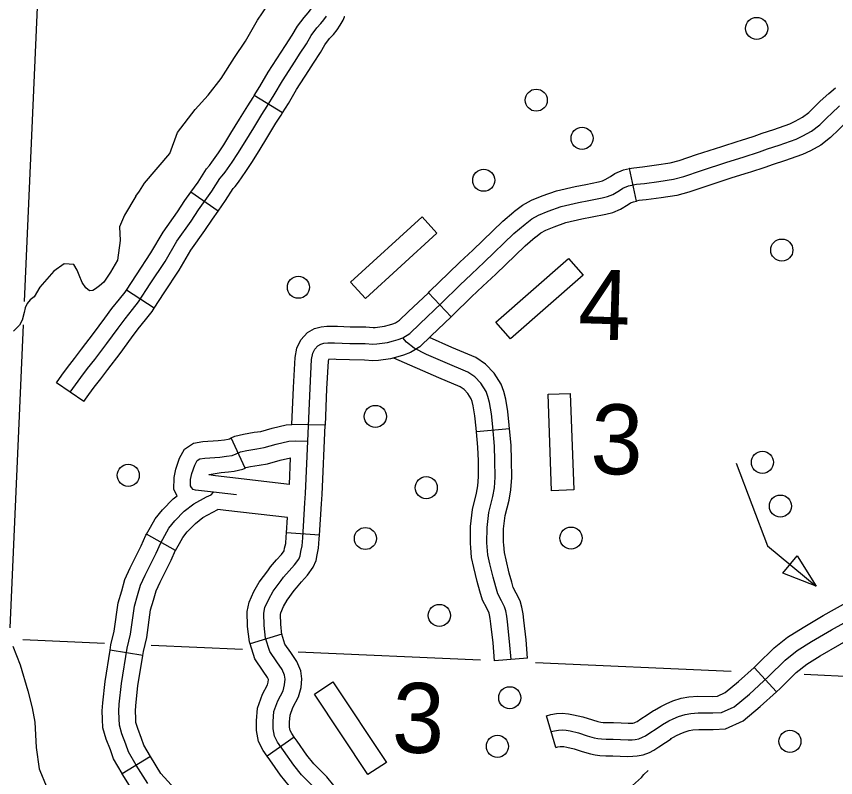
# Model space of a CAD drawing. Extents: x 653372 to 905732, y 627442 to 787275.
# Drawn here: x 705201 to 708908, y 746343 to 749788 of the extents above; entities that cross this region are included whole.
import ezdxf

# ---------------------------------------------------------------- set-up
doc = ezdxf.new("R2010")
doc.units = 0
for name, color, linetype in [('31', 7, 'Continuous'), ('32', 7, 'Continuous'), ('35', 7, 'Continuous'), ('45', 7, 'Continuous'), ('5', 7, 'Continuous'), ('56', 7, 'Continuous'), ('9', 7, 'Continuous')]:
    doc.layers.add(name, color=color, linetype=linetype)

msp = doc.modelspace()

# ---------------------------------------------------------------- linework, layer by layer
at = {"layer": '31'}
for p, q in [((707974.5, 749099), (707974.4, 749099)), ((708006.5, 748952.4), (707974.5, 749099)), ((707065, 748537.4), (707168.7, 748429))]:
    msp.add_line(p, q, dxfattribs=at)
for points in [[(708477.9, 749226), (708539.1, 749245.5), (708575.2, 749258.9), (708627.8, 749276.5), (708701.2, 749301.7), (708725.2, 749313.5), (708757.7, 749331.5), (708786.7, 749353.8), (708817.2, 749383.8), (708837.9, 749403.7), (708876.8, 749439.6), (708907.8, 749464.4)], [(706519.6, 747866), (706529.8, 748105.3), (706536.7, 748235.8), (706541.9, 748263.7), (706550.6, 748282), (706565.1, 748297.8), (706577.9, 748304.8), (706592.7, 748308.8), (706610.5, 748310.4), (706640.1, 748311), (706709.4, 748308.2), (706778.8, 748307.6), (706814.2, 748305.1), (706831.9, 748306), (706880.1, 748312.7), (706908, 748319.6), (706928.9, 748325.6), (706949.8, 748333.9), (706980.6, 748352.9), (707026.2, 748396.6), (707124.3, 748490.4), (707208, 748572.1), (707259.7, 748621.5), (707318.2, 748675.9), (707452.5, 748805.7), (707502.5, 748847.8), (707532.7, 748871.2), (707563.5, 748888), (707606.9, 748905.9), (707665.8, 748927.1), (707744.6, 748945.4), (707791.9, 748954.3), (707852.1, 748966.5), (707875.9, 748972.5), (707899.9, 748982.1), (707929.2, 749000.4), (707944.3, 749010.3), (707970.4, 749021.3), (708006.1, 749029.1), (708042.7, 749032.4), (708107.9, 749041.5), (708174, 749051.4), (708221.6, 749064), (708301.4, 749091.1), (708416.2, 749128.3), (708490, 749151.2), (708563.5, 749174.5), (708600.1, 749188.2), (708651.9, 749205.4), (708729.9, 749232.3), (708759.9, 749246.9), (708799, 749268.7), (708836, 749297.1), (708869.5, 749330.1), (708889.3, 749349), (708925.7, 749382.7)], [(709001.5, 749347.3), (708974.6, 749325.8), (708940.7, 749294.4), (708921.8, 749276.3), (708885.3, 749240.4), (708840.3, 749205.8), (708794.6, 749180.4), (708758.7, 749162.9), (708676, 749134.4), (708625.1, 749117.5), (708588, 749103.6), (708523.3, 749083.1)], [(707974.4, 749099), (707994.7, 749103.4), (708034.1, 749106.9), (708097.2, 749115.8), (708158.8, 749124.9), (708199.9, 749135.8), (708277.8, 749162.3), (708393.6, 749199.8), (708467.6, 749222.7), (708477.9, 749226)], [(707452, 748903.3), (707455.3, 748906.1), (707491.5, 748934.2), (707531.1, 748955.8), (707579.9, 748975.9), (707644.6, 748999.1), (707729.2, 749018.8), (707777.5, 749027.9), (707835.6, 749039.7), (707852.8, 749044), (707865.7, 749049.2), (707888.8, 749063.6), (707908.8, 749076.7), (707947.7, 749093.1), (707974.5, 749099)], [(708523.3, 749083.1), (708512.5, 749079.6), (708438.9, 749056.8), (708325, 749019.9), (708243.3, 748992.1), (708189.1, 748977.8), (708118.7, 748967.3), (708051.2, 748957.9), (708017.5, 748954.8), (708006.5, 748952.4)], [(707548.6, 748788.6), (707549.6, 748789.4), (707573.9, 748808.3), (707595.9, 748820.3), (707633.8, 748835.9), (707687, 748855), (707760.1, 748872), (707806.4, 748880.7), (707868.7, 748893.4), (707899.1, 748900.9), (707934, 748915), (707969.6, 748937.2), (707979.7, 748943.8), (707993.2, 748949.5), (708006.5, 748952.4)], [(707065, 748537.4), (707072.2, 748544.3), (707155.9, 748626), (707208.2, 748676.1), (707266.6, 748730.3), (707402.2, 748861.4), (707452, 748903.3)], [(707168.7, 748429), (707176.4, 748436.5), (707260.1, 748518.1), (707311.1, 748566.9), (707369.8, 748621.4), (707502.7, 748750), (707548.6, 748788.6)], [(706653.5, 748385.5), (706711.2, 748383.2), (706781.8, 748382.6), (706814.8, 748380.2), (706824.8, 748380.7), (706865.9, 748386.4), (706888.6, 748392.1), (706904.7, 748396.7), (706916.1, 748401.2), (706934.5, 748412.5), (706974.4, 748450.7), (707065, 748537.4)], [(707168.7, 748429), (707078.1, 748342.4), (707026.8, 748293.2), (706983.5, 748266.5), (706953, 748254.5), (706927.4, 748247.2), (706894.3, 748238.9), (706839.1, 748231.3), (706813.5, 748229.9), (706775.8, 748232.6), (706707.5, 748233.2), (706647.4, 748235.7)], [(706597.8, 747937.9), (706447.8, 747941.4), (706454.9, 748108.9), (706462, 748244.8), (706470, 748287.2), (706487.7, 748324.4), (706518.2, 748357.6), (706549.7, 748374.9), (706579.4, 748382.8), (706606.2, 748385.4), (706640.8, 748386.1), (706653.5, 748385.5)], [(706647.4, 748235.7), (706639.3, 748236), (706614.8, 748235.5), (706612.9, 748235.3), (706611.3, 748226.9), (706604.7, 748101.7), (706597.8, 747937.9)]]:
    msp.add_lwpolyline(points, dxfattribs=at)
at = {"layer": '32'}
for p, q in [((706405, 749351.2), (706277.5, 749430.3)), ((706113.3, 748906.3), (705990.7, 748992.7)), ((705825, 748467.8), (705699.1, 748549.3)), ((705506.5, 748044.5), (705382.7, 748129.2)), ((706235.6, 747743.8), (706172.5, 747879.9)), ((705920.8, 747371), (705790, 747444.4)), ((706572.2, 747440.1), (706422.5, 747450.1)), ((706401.3, 746992.4), (706258.2, 746947.5)), ((705772.9, 746896.2), (705624.8, 746919.9)), ((706458.5, 746525.8), (706335.4, 746440.1)), ((705807.6, 746438.5), (705680, 746359.6))]:
    msp.add_line(p, q, dxfattribs=at)
for points in [[(706277.5, 749430.3), (706303.1, 749471.5), (706340.4, 749536.2), (706398.9, 749625.6), (706419.2, 749657), (706449, 749703.5), (706472.3, 749743.3), (706502.9, 749783.8), (706521.3, 749804), (706531.7, 749817.2), (706540.2, 749829.3), (706543.3, 749834.7), (706549, 749850.9), (706562.1, 749872.2), (706567, 749878.7)], [(705444.6, 748086.8), (705467.8, 748120.7), (705492.7, 748154.4), (705523.1, 748194.3), (705555.3, 748235.6), (705610.1, 748307.4), (705660.9, 748377.6), (705692.7, 748420), (705726.3, 748461.5), (705753.8, 748495.9), (705806.7, 748577.5), (705873.5, 748678.6), (705927.6, 748770.8), (705992.3, 748861.8), (706025.7, 748912.2), (706085.3, 748996.7), (706121.5, 749053.7), (706132.1, 749066.2), (706145.4, 749083.1), (706177.8, 749128.6), (706202.8, 749167.2), (706235.4, 749219.8), (706274.9, 749284.1), (706311.7, 749343.9), (706335.4, 749381.3), (706367.5, 749433), (706404.3, 749496.9), (706461.8, 749584.8), (706482.3, 749616.5), (706512.9, 749664.2), (706534.8, 749701.7), (706560.6, 749735.9), (706578.5, 749755.5), (706591.8, 749772.3), (706603.4, 749788.8)], [(706405, 749351.2), (706431.8, 749394.5), (706468.2, 749457.6), (706524.7, 749543.9), (706545.4, 749575.9), (706576.9, 749625), (706597.3, 749660), (706618.4, 749687.9), (706635.7, 749706.9), (706652, 749727.5), (706666.6, 749748.3), (706680.2, 749771.6), (706685.3, 749786.1), (706686, 749787.4), (706686.7, 749788.2)], [(705990.7, 748992.7), (706023, 749038.5), (706060.9, 749098.2), (706074, 749113.7), (706085.4, 749128.1), (706115.7, 749170.7), (706139.5, 749207.4), (706171.5, 749259.2), (706211, 749323.4), (706248.1, 749383.6), (706271.8, 749421.1), (706277.5, 749430.3)], [(706113.3, 748906.3), (706147.6, 748954.9), (706182.1, 749009.2), (706190.2, 749018.7), (706205.4, 749038), (706239.8, 749086.4), (706266.2, 749127.1), (706299.2, 749180.4), (706338.8, 749244.8), (706375.3, 749304.2), (706398.9, 749341.4), (706405, 749351.2)], [(705699.1, 748549.3), (705744, 748618.6), (705809.8, 748718.2), (705864.6, 748811.6), (705930.5, 748904.3), (705963.8, 748954.5), (705990.7, 748992.7)], [(705825, 748467.8), (705869.5, 748536.5), (705937.2, 748638.9), (705990.6, 748730), (706054.1, 748819.4), (706087.6, 748869.8), (706113.3, 748906.3)], [(705382.7, 748129.2), (705406.6, 748164.1), (705432.7, 748199.5), (705463.7, 748240.1), (705495.9, 748281.4), (705549.9, 748352.2), (705600.5, 748422.1), (705633.5, 748466.1), (705667.9, 748508.6), (705693, 748539.9), (705699.1, 748549.3)], [(705506.5, 748044.5), (705528.9, 748077.2), (705552.7, 748109.4), (705582.4, 748148.4), (705614.7, 748189.8), (705670.3, 748262.7), (705721.3, 748333.1), (705751.9, 748373.9), (705784.7, 748414.5), (705814.7, 748451.9), (705825, 748467.8)], [(706172.5, 747879.9), (706189.8, 747888), (706229.2, 747897.5), (706276.5, 747905.7), (706306.8, 747910), (706358.2, 747924.5), (706422.2, 747939.1), (706447.8, 747941.4)], [(706572.2, 747440.1), (706581.7, 747581.5), (706584.4, 747624.4), (706597.8, 747937.9)], [(705927.7, 747618.3), (705913, 747647.2), (705914.7, 747701.3), (705922.2, 747739.4), (705939.7, 747787.9), (705961.8, 747829.1), (706002, 747856.7), (706045, 747863.7), (706114.2, 747868.5), (706142.6, 747871.7), (706158.6, 747873.9), (706165.5, 747876.7), (706172.5, 747879.9)], [(706196.4, 747622), (706158, 747626.5), (706093.4, 747634.8), (706011.6, 747643.4), (706000.6, 747647.4), (705992.8, 747655.8), (705988.6, 747664.1), (705989.4, 747692.8), (705994.7, 747719.3), (706008.4, 747757.3), (706019.3, 747777.6), (706030.6, 747785.4), (706053.6, 747789.2), (706120.9, 747793.8), (706152.1, 747797.3), (706178, 747800.9), (706195.2, 747807.8), (706214.7, 747816.8), (706244.4, 747824), (706288.2, 747831.6), (706322.3, 747836.5), (706376.7, 747851.8), (706433.9, 747864.9), (706465, 747867.7), (706519.6, 747866)], [(706550.1, 746295.8), (706491.3, 746355.1), (706455.7, 746399.2), (706409.2, 746465.5), (706382.5, 746503.8), (706368.8, 746530.9), (706362.5, 746563.8), (706362.2, 746596.5), (706366, 746641.3), (706383.2, 746690.4), (706407.6, 746735.8), (706414.5, 746762.2), (706416.5, 746788.8), (706414.6, 746805.9), (706403.2, 746831.6), (706380, 746866.3), (706347.5, 746913.3), (706328.7, 746973.3), (706322, 747031.6), (706320, 747087.4), (706325.6, 747112.7), (706342.5, 747151), (706363, 747186.8), (706398.4, 747234.2), (706409.7, 747249.3), (706434.8, 747278.2), (706459.2, 747305.4), (706478.2, 747332.1), (706484.7, 747347), (706488.3, 747365.7), (706494, 747392.2), (706496.3, 747428.5), (706506.8, 747586.4), (706509.6, 747628.5), (706519.6, 747866)], [(706235.5, 747743.8), (706239.5, 747745.7), (706259.7, 747750.6), (706299.9, 747757.5), (706337.9, 747762.9), (706395.2, 747779.1), (706441.3, 747789.6)], [(706436.2, 747669.9), (706441.3, 747789.6)], [(706436.2, 747669.9), (706167.1, 747700.9), (706102.1, 747709.3), (706071.9, 747712.5), (706072.9, 747715.3), (706127.5, 747723.4), (706161.3, 747727.2), (706186.8, 747730.4), (706224.9, 747738.9), (706235.6, 747743.8)], [(705795.2, 746315.9), (705743.5, 746399.5), (705708.9, 746458.7), (705696.8, 746493.9), (705678.8, 746541.1), (705666.9, 746580.2), (705666.2, 746608.8), (705664.9, 746643.7), (705666.6, 746674.7), (705676.4, 746768.1), (705702.1, 746928.4), (705717.1, 746991.5), (705734.9, 747118.2), (705749.5, 747167.4), (705762.6, 747214.2), (705783.3, 747259.3), (705833.5, 747359.1), (705854.2, 747405.7), (705873.1, 747439.2), (705891.1, 747472), (705918.4, 747505.2), (705960.8, 747548.9), (706003.6, 747582.5), (706061.1, 747614), (706082.2, 747621.9), (706093.4, 747634.8)], [(705790, 747444.4), (705807.5, 747475.6), (705828.7, 747514.2), (705862.4, 747555.2), (705910.5, 747604.8), (705927.7, 747618.3)], [(705920.8, 747371), (705938.6, 747402.8), (705953.5, 747429.7), (705974.4, 747455.2), (706011, 747493), (706045.1, 747519.7), (706112.4, 747556.7)], [(706427.2, 747519.9), (706148.9, 747552), (706112.4, 747556.7)], [(706422.5, 747450.1), (706427.2, 747519.9)], [(705624.8, 746919.9), (705628.5, 746943.1), (705643.4, 747005.4), (705661.4, 747134.2), (705677.5, 747188.1), (705691.9, 747240.1), (705715.7, 747291.8), (705765.7, 747391.2), (705787.1, 747439.4), (705790, 747444.4)], [(706258.2, 746947.5), (706255, 746957.6), (706247.1, 747026), (706244.8, 747094.4), (706254, 747136.2), (706275.5, 747184.9), (706300.2, 747227.9), (706338.3, 747279.1), (706351.3, 747296.4), (706378.6, 747327.9), (706400.6, 747352.3), (706412.6, 747369.1), (706412.6, 747369.3), (706414.8, 747380.6), (706419.5, 747402.4), (706421.4, 747433.3), (706422.5, 747450.1)], [(706402.4, 746988.9), (706396.8, 747037.3), (706395.3, 747080.5), (706397.3, 747089.2), (706409.6, 747117.1), (706425.8, 747145.6), (706458.4, 747189.2), (706468.1, 747202.1), (706491, 747228.6), (706517.9, 747258.4), (706543.9, 747295), (706556.8, 747324.7), (706561.8, 747350.8), (706568.5, 747381.9), (706571.1, 747423.6), (706572.2, 747440.1)], [(705772.9, 746896.2), (705775.7, 746913.8), (705790.9, 746977.6), (705808.4, 747102.2), (705821.6, 747146.6), (705833.2, 747188.4), (705850.9, 747226.8), (705901.3, 747326.9), (705921.4, 747372), (705920.8, 747371)], [(706458.5, 746525.8), (706447, 746542.4), (706440.4, 746555.4), (706437.4, 746571.2), (706437.3, 746593.7), (706439.9, 746625.5), (706452.1, 746660.1), (706478, 746708.2), (706488.8, 746749.9), (706491.8, 746790.2), (706487.8, 746825.6), (706469.2, 746867.9), (706442, 746908.5), (706415.7, 746946.6), (706401.3, 746992.4)], [(706335.4, 746440.1), (706317.9, 746465.3), (706297.1, 746506.4), (706287.5, 746556.5), (706287.2, 746599.4), (706292.1, 746657.1), (706314.4, 746720.8), (706337.3, 746763.3), (706340.2, 746774.6), (706341.1, 746786.6), (706337.2, 746795.4), (706318, 746824.1), (706279.4, 746880), (706258.2, 746947.5)], [(705680, 746359.6), (705679.2, 746360.9), (705640.4, 746427.2), (705626.3, 746468.4), (705607.9, 746516.7), (705592.1, 746568), (705591.2, 746606.6), (705589.8, 746644.4), (705591.8, 746680.6), (705602, 746777.9), (705624.8, 746919.9)], [(705807.8, 746438.2), (705777.4, 746490.1), (705767.3, 746519.4), (705749.8, 746565.4), (705741.6, 746592.3), (705741.1, 746611.1), (705740, 746643), (705741.4, 746668.7), (705750.7, 746758.2), (705772.9, 746896.2)], [(706758.8, 746083.7), (706713, 746172.8), (706691.9, 746219.7), (706675.6, 746250.8), (706654.5, 746281.7), (706637.2, 746307), (706606.2, 746345.8), (706547.2, 746405.2), (706515.6, 746444.4), (706470.7, 746508.4), (706458.5, 746525.8)], [(706071.2, 746000.9), (706066.1, 746008.1), (706057.9, 746023.1), (706048.9, 746045.6), (706047.3, 746061.2), (706044.8, 746113.8), (706014.3, 746180.2), (705978.1, 746228.6), (705918.5, 746292.7), (705855.2, 746361.4), (705807.6, 746438.5)], [(706625.4, 746015.1), (706577.8, 746107.7), (706556.9, 746154.1), (706546.7, 746173.5), (706530.7, 746197.1), (706516.7, 746217.6), (706494, 746245.8), (706435.3, 746305), (706395.7, 746354.1), (706347.7, 746422.5), (706335.4, 746440.1)], [(705948.8, 745914.2), (705938.6, 745928.6), (705921.9, 745959.2), (705902, 746009.2), (705897.6, 746049.6), (705896.3, 746077.7), (705884.6, 746103.1), (705862.8, 746132.3), (705808.4, 746190.9), (705735.2, 746270.4), (705680, 746359.6)]]:
    msp.add_lwpolyline(points, dxfattribs=at)
at = {"layer": '35'}
for points in [[(706069.4, 749431.3), (706128.1, 749507.3), (706188, 749602.1), (706238.2, 749676.5), (706292.4, 749770.6), (706337.4, 749837.2), (706360.5, 749888.5)], [(705741.6, 748973.8), (705757.9, 748996.8), (705781, 749034), (705894.8, 749167.6), (705929.6, 749262.8), (706010.6, 749367.2), (706069.4, 749431.3)], [(705741.6, 748973.8), (705690.1, 748888.1), (705667.2, 748835.4), (705670.5, 748774.2), (705657.7, 748684.1), (705626.8, 748630.2), (705597.2, 748585.9), (705577.2, 748567.9), (705558.2, 748555.2), (705546.5, 748547.6), (705532.2, 748545.4), (705515.9, 748560), (705498.9, 748584.4), (705484.8, 748617.6), (705476.7, 748640), (705460.6, 748665.3), (705440.2, 748667.1), (705416.7, 748667.8), (705370.9, 748635)], [(705370.9, 748635), (705306.8, 748562.2), (705281.9, 748519.3), (705263.8, 748504.7), (705250, 748488.3), (705240.6, 748469.1), (705236.4, 748448), (705227.4, 748413.8), (705215.2, 748391.1), (705187.8, 748363.6)], [(707343.2, 745393.1), (707403, 745481.9), (707444.8, 745551.9), (707462.1, 745580.1), (707483.7, 745613.7), (707496.8, 745640.8), (707503.1, 745668), (707505.3, 745696.7), (707506.4, 745730.9), (707513, 745770.5), (707532.1, 745812.4), (707554.3, 745866.5), (707576.7, 745927.5), (707616, 746007.2), (707649, 746055.4), (707690.2, 746106.2), (707739.5, 746151.3), (707814.8, 746192.9), (707908.1, 746244.9), (707952.8, 746273.7), (707988.1, 746306.9), (708028.9, 746342.7), (708040, 746356.6), (708060.3, 746375.6)]]:
    msp.add_lwpolyline(points, dxfattribs=at)
at = {"layer": '45'}
for p, q in [((707432.3, 747921.6), (707282.9, 747907.8)), ((707513.8, 746884.1), (707364.4, 746871.5)), ((708640.5, 746730.9), (708539.5, 746841.8)), ((707642.4, 746479), (707600.1, 746622.9))]:
    msp.add_line(p, q, dxfattribs=at)
for points in [[(707439.1, 746877.8), (707432.2, 746959.4), (707422.5, 747047.6), (707419.4, 747074), (707415.5, 747097.3), (707409.8, 747115.3), (707396, 747143.6), (707379.1, 747175.1), (707370, 747206.4), (707358.1, 747249.3), (707343.7, 747311), (707334.8, 747350.5), (707330.2, 747404.9), (707330.8, 747474.3), (707339, 747543.2), (707356.7, 747614.8), (707364.1, 747654), (707367.1, 747702.7), (707366.2, 747778.1), (707364.3, 747842.4), (707356.1, 747931), (707350.1, 747990), (707341.6, 748040.6), (707334.6, 748067.1), (707326.1, 748090.6), (707303.2, 748127.7), (707275.4, 748156.5), (707244.3, 748177.5), (707141.8, 748220.9), (707056.2, 748258.3), (707001.3, 748287.1), (706965.7, 748312.9), (706949.8, 748333.9)], [(707432.3, 747921.6), (707430.8, 747938.2), (707424.5, 748000), (707415, 748056.4), (707406.3, 748089.6), (707393.9, 748123.5), (707362.7, 748174), (707323.9, 748214.2), (707280.3, 748243.7), (707171.4, 748289.8), (707069.6, 748334.3)], [(707282.9, 747907.8), (707281.5, 747923.7), (707275.8, 747980), (707268.2, 748024.8), (707263, 748044.7), (707258.2, 748057.7), (707243.6, 748081.4), (707226.9, 748098.7), (707208.3, 748111.3), (707112.2, 748152), (706908.7, 748240.9)], [(707256.7, 747384.2), (707255.2, 747402), (707255.8, 747479), (707265.1, 747556.7), (707283.4, 747630.7), (707289.5, 747663.3), (707292, 747704.6), (707291.2, 747776.5), (707289.4, 747837.8), (707282.9, 747907.8)], [(707406.2, 747396.7), (707405.3, 747407.7), (707405.7, 747469.5), (707413, 747529.8), (707430, 747598.8), (707438.6, 747644.8), (707442.1, 747700.8), (707441.2, 747779.6), (707439.2, 747847), (707432.3, 747921.6)], [(707364.4, 746871.5), (707357.6, 746952.1), (707348, 747039.1), (707345.2, 747063.4), (707342.4, 747079.8), (707340, 747087.4), (707329.2, 747109.4), (707309.3, 747146.6), (707297.8, 747185.9), (707285.4, 747230.8), (707270.6, 747294.2), (707260.5, 747339.1), (707256.7, 747384.2)], [(707513.8, 746884.1), (707506.9, 746966.6), (707497, 747056), (707493.7, 747084.6), (707488.6, 747114.9), (707479.7, 747143.2), (707462.7, 747177.8), (707448.9, 747203.6), (707442.1, 747226.9), (707430.8, 747267.9), (707416.8, 747327.7), (707409.1, 747361.9), (707406.2, 747396.7)], [(708539.5, 746841.8), (708553.1, 746854.2), (708630, 746930.2), (708690.7, 746978.6), (708760.5, 747022.8), (708852, 747076), (708968.2, 747141.2), (708987, 747151.1)], [(708392, 746637.3), (708448.6, 746663.2), (708517.8, 746720.5), (708604.8, 746799.8), (708679.9, 746874.1), (708734.3, 746917.4), (708799.4, 746958.7), (708889.2, 747010.9), (709004, 747075.3)], [(708640.5, 746730.9), (708656.4, 746745.4), (708729.8, 746817.9), (708777.9, 746856.3), (708838.4, 746894.6), (708926.4, 746945.8), (709008.6, 746991.9)], [(708087.6, 746648.4), (708117.4, 746665.1), (708141.7, 746677.4), (708171.8, 746689.7), (708209, 746701.6), (708243.6, 746707.7), (708283.8, 746710.8), (708350.9, 746710.2), (708373.8, 746711.4), (708408.4, 746727.3), (708468.6, 746777.1), (708539.5, 746841.8)], [(708161.2, 746517.7), (708188.1, 746532.8), (708204, 746540.9), (708223.1, 746548.7), (708245, 746555.7), (708262.4, 746558.7), (708289, 746560.8), (708354.2, 746560.2), (708410.2, 746563.2), (708488.8, 746599.1), (708567, 746663.9), (708640.5, 746730.9)], [(707600.1, 746622.9), (707619.4, 746628.6), (707645.6, 746632.3), (707671, 746634.2), (707699.4, 746631.9), (707721.8, 746627.3), (707764.7, 746618.4), (707807, 746603.6), (707832, 746596.4), (707844.9, 746594.3), (707855.8, 746592.4), (707871.9, 746592), (707902.5, 746591.5), (707937.7, 746590.4), (707969.4, 746589), (707983.9, 746589.3), (707990.6, 746589.8), (707996, 746590.8), (708002.9, 746593.5), (708009.6, 746597), (708026.5, 746608.1), (708054.4, 746626.2), (708084.4, 746646.5), (708087.6, 746648.4)], [(707621.2, 746550.9), (707635.4, 746555.1), (707653.7, 746557.7), (707670.8, 746559), (707688.8, 746557.5), (707706.6, 746553.8), (707744.6, 746545.9), (707784.3, 746532.2), (707815.5, 746523.1), (707832.5, 746520.4), (707848.2, 746517.6), (707870.2, 746517), (707900.8, 746516.5), (707935, 746515.5), (707968.4, 746514), (707987.3, 746514.4), (708000.4, 746515.3), (708016.7, 746518.4), (708034, 746525.1), (708047.7, 746532.3), (708067.4, 746545.3), (708095.9, 746563.8), (708123.9, 746582.7), (708152.7, 746599), (708172.8, 746609.1), (708197.4, 746619.2), (708227, 746628.7), (708253, 746633.2), (708286.4, 746635.8), (708330.5, 746635.4), (708352.5, 746635.2), (708392, 746637.3)], [(707642.4, 746479), (707651.3, 746481.6), (707661.8, 746483.1), (707670.6, 746483.7), (707678.1, 746483.1), (707691.4, 746480.4), (707724.6, 746473.5), (707761.5, 746460.7), (707799, 746449.8), (707820.1, 746446.4), (707840.6, 746442.8), (707868.5, 746442), (707899.1, 746441.5), (707932.2, 746440.5), (707967.5, 746439), (707990.7, 746439.4), (708010.2, 746440.8), (708037.4, 746446), (708065.1, 746456.7), (708085.8, 746467.7), (708108.4, 746482.4), (708137.4, 746501.3), (708163.4, 746518.9), (708161.2, 746517.7)]]:
    msp.add_lwpolyline(points, dxfattribs=at)
at = {"layer": '5'}
for points in [[(705400.8, 752221.9), (705236.8, 748498.1)], [(705232.1, 748392), (705171.7, 747020.4)], [(705599, 746949.8), (705230.4, 746966.2)], [(706224.4, 746922), (705810.4, 746940.4)], [(707301.6, 746874), (706476.2, 746910.8)], [(708434.5, 746823.6), (707549.2, 746863)], [(709011.7, 746797.9), (708765.2, 746808.9)]]:
    msp.add_lwpolyline(points, dxfattribs=at)
at = {"layer": '56'}
for p, q in [((708668.8, 747268.4), (708733.9, 747346.9)), ((708733.9, 747346.9), (708819.1, 747210)), ((708819.1, 747210), (708668.8, 747268.4))]:
    msp.add_line(p, q, dxfattribs=at)
for points in [[(706780.6, 748512), (706713.3, 748585.9), (707036.7, 748880.5), (707104.1, 748806.5)], [(707436.1, 748329.2), (707370.2, 748404.4), (707699.4, 748692.6), (707765.3, 748617.3)], [(707607, 748078.1), (707706.9, 748081.8), (707722.9, 747644.6), (707622.9, 747640.9)], [(706549.5, 746720.9), (706632.9, 746776.2), (706874.9, 746411.7), (706791.5, 746356.4)]]:
    msp.add_lwpolyline(points, close=True, dxfattribs=at)
msp.add_lwpolyline([(708457.5, 747766.6), (708599.8, 747391.9), (708819.1, 747210)], dxfattribs=at)
for centre in [(708550.7, 749733.6), (707553.1, 749409), (707760.7, 749236.3), (707315.6, 749046.5), (708664.4, 748730.3), (706477.1, 748562.2), (706825.3, 747977.3), (708576.8, 747769.9), (705706.9, 747711), (707055.3, 747654.9), (708658, 747571.6), (706780.3, 747425), (707710.5, 747426.9), (707114.9, 747076.7), (707433.5, 746704), (707377.7, 746484.2), (708701, 746507.1)]:
    msp.add_circle(centre, 50, dxfattribs=at)
at = {"layer": '9'}
for points in [[(705185.1, 746937.7), (705218.1, 746852.7), (705253.1, 746736.2), (705272.1, 746658.6), (705284.2, 746593.3), (705290.6, 746479.6), (705304.6, 746382.8)], [(705304.6, 746382.8), (705306.6, 746375.1), (705335.9, 746305.8), (705354.6, 746266.7), (705377.9, 746234.7), (705413.9, 746152.4), (705453.9, 746061.4), (705480.4, 745995), (705498.9, 745946), (705554.9, 745864.5), (705593.3, 745816.3), (705646.2, 745737.1), (705669.4, 745702.2), (705683, 745680.4), (705696.6, 745658.6), (705711.7, 745641.1), (705725.5, 745625), (705737.6, 745603.2), (705766.3, 745561), (705800, 745498.7), (705814, 745478.5)]]:
    msp.add_lwpolyline(points, dxfattribs=at)

# ---------------------------------------------------------------- texts
at = {"layer": '56'}
for s, p in [('4', (707740, 748328.2)), ('3', (707795.6, 747719.1)), ('3', (706897.5, 746458))]:
    msp.add_text(s, height=316.8, rotation=358.28, dxfattribs=at).set_placement(p)

doc.saveas('drawing.dxf')
